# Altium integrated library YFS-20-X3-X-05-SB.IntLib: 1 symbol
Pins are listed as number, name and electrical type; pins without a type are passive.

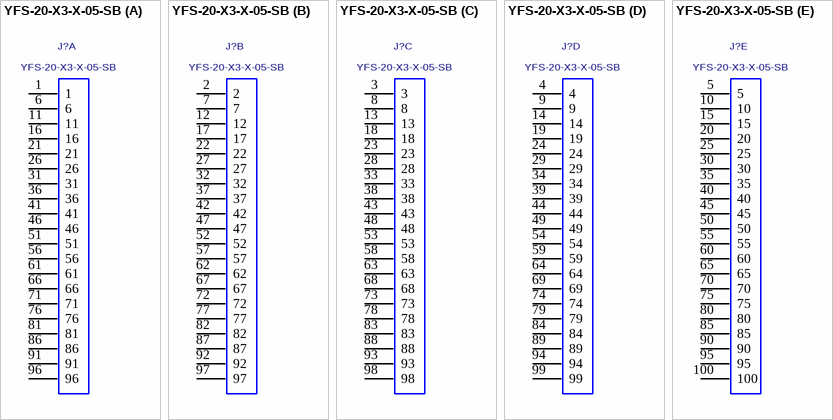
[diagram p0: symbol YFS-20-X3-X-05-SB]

## YFS-20-X3-X-05-SB
designator J?
.050[1.27] MULTI-ROW SOCKET ASSEMBLY.; MANUFACTURER: SAMTEC
footprint YFS-20-X3-X-05-SB
part A pins: 1, 6, 11, 16, 21, 26, 31, 36, 41, 46, 51, 56, 61, 66, 71, 76, 81, 86, 91, 96
part B pins: 2, 7, 12, 17, 22, 27, 32, 37, 42, 47, 52, 57, 62, 67, 72, 77, 82, 87, 92, 97
part C pins: 3, 8, 13, 18, 23, 28, 33, 38, 43, 48, 53, 58, 63, 68, 73, 78, 83, 88, 93, 98
part D pins: 4, 9, 14, 19, 24, 29, 34, 39, 44, 49, 54, 59, 64, 69, 74, 79, 84, 89, 94, 99
part E pins: 5, 10, 15, 20, 25, 30, 35, 40, 45, 50, 55, 60, 65, 70, 75, 80, 85, 90, 95, 100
